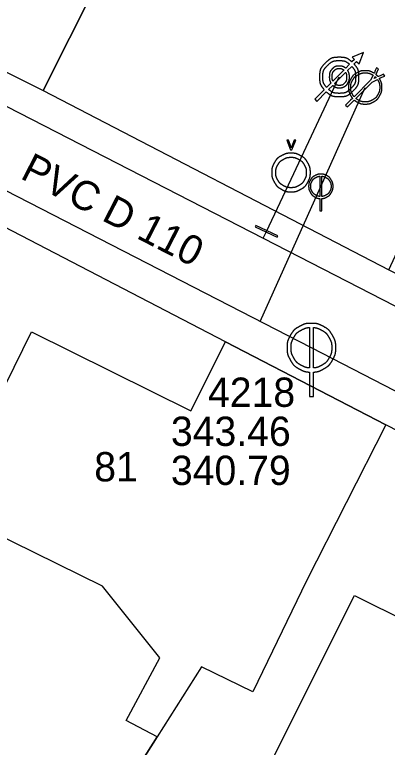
# Model space of a CAD drawing. Extents: x -559654 to -559448, y -1076607 to -1076478.
# Drawn here: x -559557.35 to -559538.26, y -1076565.25 to -1076527.73 of the extents above; entities that cross this region are included whole.
import ezdxf

# ---------------------------------------------------------------- set-up
doc = ezdxf.new("R2010")
doc.units = 0
for name, color, linetype in [('Armatura vodovodní', 7, 'Continuous'), ('Default', 7, 'Continuous'), ('Kanalizační přípojka', 7, 'Continuous'), ('Kanalizační stoka', 7, 'Continuous'), ('Kanalizační šachta', 7, 'Continuous'), ('Odběrné místo', 7, 'Continuous'), ('Odběrné místo na kanalizaci', 7, 'Continuous'), ('Parcela-polygon', 7, 'Continuous'), ('Parcela-text', 7, 'Continuous'), ('Popis šachty', 7, 'Continuous'), ('Vodovodní přípojka', 7, 'Continuous'), ('Vodovodní řad', 7, 'Continuous'), ('Vodovodní šachta', 7, 'Continuous'), ('Řad vodovodní popis', 7, 'Continuous')]:
    doc.layers.add(name, color=color, linetype=linetype)

msp = doc.modelspace()

# ---------------------------------------------------------------- linework, layer by layer
at = {"layer": 'Armatura vodovodní'}
msp.add_lwpolyline([(-559543.905, -1076539.127), (-559543.872, -1076539.056), (-559545.002, -1076538.523), (-559545.036, -1076538.594)], close=True, dxfattribs=at)
at = {"layer": 'Default'}
for points in [[(-559540.724, -1076529.913), (-559541.003, -1076529.913), (-559541.241, -1076530.012), (-559541.438, -1076530.208)], [(-559541.319, -1076530.326), (-559541.155, -1076530.162), (-559540.956, -1076530.08), (-559540.724, -1076530.08)], [(-559540.073, -1076530.15), (-559540.257, -1076529.992), (-559540.474, -1076529.913), (-559540.724, -1076529.913)], [(-559540.724, -1076530.08), (-559540.52, -1076530.08), (-559540.343, -1076530.144), (-559540.191, -1076530.27)], [(-559541.438, -1076530.208), (-559541.635, -1076530.405), (-559541.733, -1076530.642), (-559541.733, -1076530.92)], [(-559541.565, -1076530.92), (-559541.565, -1076530.688), (-559541.483, -1076530.49), (-559541.319, -1076530.326)], [(-559541.087, -1076530.514), (-559541.183, -1076530.615), (-559541.231, -1076530.754), (-559541.231, -1076530.933)], [(-559540.716, -1076530.362), (-559540.868, -1076530.362), (-559540.991, -1076530.413), (-559541.087, -1076530.514)], [(-559540.976, -1076530.589), (-559540.903, -1076530.52), (-559540.816, -1076530.486), (-559540.716, -1076530.486)], [(-559540.449, -1076530.433), (-559540.529, -1076530.386), (-559540.618, -1076530.362), (-559540.716, -1076530.362)], [(-559540.716, -1076530.486), (-559540.645, -1076530.486), (-559540.581, -1076530.504), (-559540.525, -1076530.539)], [(-559540.394, -1076530.472), (-559540.411, -1076530.459), (-559540.429, -1076530.445), (-559540.449, -1076530.433)], [(-559540.084, -1076530.376), (-559539.95, -1076530.53), (-559539.882, -1076530.711), (-559539.882, -1076530.92)], [(-559539.715, -1076530.92), (-559539.715, -1076530.665), (-559539.799, -1076530.443), (-559539.965, -1076530.256)], [(-559541.085, -1076530.935), (-559541.085, -1076530.773), (-559541.048, -1076530.658), (-559540.976, -1076530.589)], [(-559540.525, -1076530.539), (-559540.512, -1076530.548), (-559540.499, -1076530.557), (-559540.488, -1076530.566)], [(-559540.395, -1076530.688), (-559540.395, -1076530.689), (-559540.395, -1076530.69), (-559540.394, -1076530.691)], [(-559540.394, -1076530.691), (-559540.365, -1076530.756), (-559540.35, -1076530.832), (-559540.35, -1076530.919)], [(-559540.266, -1076530.632), (-559540.274, -1076530.616), (-559540.283, -1076530.6), (-559540.293, -1076530.585)], [(-559540.203, -1076530.92), (-559540.203, -1076530.813), (-559540.224, -1076530.717), (-559540.266, -1076530.632)], [(-559539.813, -1076530.709), (-559539.949, -1076530.782), (-559540.055, -1076530.888), (-559540.132, -1076531.025)], [(-559540.035, -1076531.081), (-559539.968, -1076530.962), (-559539.876, -1076530.87), (-559539.757, -1076530.807)], [(-559539.392, -1076530.599), (-559539.537, -1076530.599), (-559539.677, -1076530.635), (-559539.813, -1076530.709)], [(-559539.757, -1076530.807), (-559539.639, -1076530.743), (-559539.517, -1076530.711), (-559539.392, -1076530.711)], [(-559538.973, -1076530.709), (-559539.109, -1076530.635), (-559539.249, -1076530.599), (-559539.392, -1076530.599)], [(-559539.392, -1076530.711), (-559539.268, -1076530.711), (-559539.146, -1076530.743), (-559539.028, -1076530.807)], [(-559539.028, -1076530.807), (-559539.013, -1076530.814), (-559538.999, -1076530.823), (-559538.986, -1076530.831)], [(-559538.935, -1076530.731), (-559538.947, -1076530.724), (-559538.96, -1076530.716), (-559538.973, -1076530.709)], [(-559538.891, -1076530.902), (-559538.874, -1076530.918), (-559538.858, -1076530.934), (-559538.841, -1076530.952)], [(-559538.738, -1076530.901), (-559538.769, -1076530.864), (-559538.803, -1076530.829), (-559538.84, -1076530.799)], [(-559541.733, -1076530.92), (-559541.733, -1076531.171), (-559541.653, -1076531.389), (-559541.493, -1076531.573)], [(-559541.373, -1076531.454), (-559541.501, -1076531.302), (-559541.565, -1076531.125), (-559541.565, -1076530.92)], [(-559541.231, -1076530.933), (-559541.231, -1076531.027), (-559541.211, -1076531.116), (-559541.169, -1076531.201)], [(-559541.169, -1076531.201), (-559541.164, -1076531.212), (-559541.159, -1076531.222), (-559541.153, -1076531.233)], [(-559541.051, -1076531.13), (-559541.073, -1076531.074), (-559541.085, -1076531.009), (-559541.085, -1076530.935)], [(-559540.719, -1076531.352), (-559540.815, -1076531.352), (-559540.897, -1076531.321), (-559540.964, -1076531.257)], [(-559540.454, -1076531.24), (-559540.523, -1076531.315), (-559540.611, -1076531.352), (-559540.719, -1076531.352)], [(-559540.456, -1076531.408), (-559540.376, -1076531.364), (-559540.313, -1076531.299), (-559540.269, -1076531.213)], [(-559540.35, -1076530.919), (-559540.35, -1076531.057), (-559540.385, -1076531.164), (-559540.454, -1076531.24)], [(-559540.269, -1076531.213), (-559540.225, -1076531.127), (-559540.203, -1076531.029), (-559540.203, -1076530.92)], [(-559540.132, -1076531.025), (-559540.208, -1076531.162), (-559540.247, -1076531.305), (-559540.247, -1076531.453)], [(-559540.134, -1076531.453), (-559540.134, -1076531.324), (-559540.101, -1076531.2), (-559540.035, -1076531.081)], [(-559539.882, -1076530.92), (-559539.882, -1076531.152), (-559539.965, -1076531.35), (-559540.129, -1076531.514)], [(-559540.011, -1076531.633), (-559539.814, -1076531.436), (-559539.715, -1076531.199), (-559539.715, -1076530.92)], [(-559538.771, -1076531.046), (-559538.764, -1076531.057), (-559538.757, -1076531.069), (-559538.749, -1076531.081)], [(-559538.749, -1076531.081), (-559538.683, -1076531.2), (-559538.65, -1076531.324), (-559538.65, -1076531.453)], [(-559538.653, -1076531.024), (-559538.659, -1076531.014), (-559538.665, -1076531.004), (-559538.671, -1076530.994)], [(-559538.538, -1076531.453), (-559538.538, -1076531.305), (-559538.576, -1076531.162), (-559538.653, -1076531.024)], [(-559540.724, -1076531.759), (-559540.933, -1076531.759), (-559541.114, -1076531.693), (-559541.267, -1076531.561)], [(-559541.057, -1076531.351), (-559541.036, -1076531.369), (-559541.013, -1076531.386), (-559540.988, -1076531.401)], [(-559540.988, -1076531.401), (-559540.909, -1076531.45), (-559540.818, -1076531.475), (-559540.717, -1076531.475)], [(-559540.129, -1076531.514), (-559540.293, -1076531.677), (-559540.492, -1076531.759), (-559540.724, -1076531.759)], [(-559540.724, -1076531.927), (-559540.445, -1076531.927), (-559540.208, -1076531.829), (-559540.011, -1076531.633)], [(-559540.717, -1076531.475), (-559540.624, -1076531.475), (-559540.537, -1076531.452), (-559540.456, -1076531.408)], [(-559540.247, -1076531.453), (-559540.247, -1076531.601), (-559540.209, -1076531.743), (-559540.133, -1076531.879)], [(-559540.036, -1076531.822), (-559540.101, -1076531.705), (-559540.134, -1076531.582), (-559540.134, -1076531.453)], [(-559538.65, -1076531.453), (-559538.65, -1076531.582), (-559538.683, -1076531.705), (-559538.748, -1076531.823)], [(-559538.65, -1076531.879), (-559538.575, -1076531.743), (-559538.538, -1076531.601), (-559538.538, -1076531.453)], [(-559541.386, -1076531.681), (-559541.2, -1076531.845), (-559540.979, -1076531.927), (-559540.724, -1076531.927)], [(-559540.133, -1076531.879), (-559540.107, -1076531.928), (-559540.076, -1076531.973), (-559540.041, -1076532.014)], [(-559539.96, -1076531.933), (-559539.989, -1076531.899), (-559540.014, -1076531.862), (-559540.036, -1076531.822)], [(-559539.761, -1076532.097), (-559539.802, -1076532.074), (-559539.839, -1076532.049), (-559539.872, -1076532.02)], [(-559538.748, -1076531.823), (-559538.813, -1076531.94), (-559538.905, -1076532.032), (-559539.023, -1076532.097)], [(-559538.967, -1076532.195), (-559538.831, -1076532.12), (-559538.726, -1076532.014), (-559538.65, -1076531.879)], [(-559539.954, -1076532.101), (-559539.912, -1076532.137), (-559539.866, -1076532.168), (-559539.817, -1076532.194)], [(-559539.817, -1076532.194), (-559539.681, -1076532.27), (-559539.54, -1076532.308), (-559539.392, -1076532.308)], [(-559539.392, -1076532.195), (-559539.52, -1076532.195), (-559539.643, -1076532.162), (-559539.761, -1076532.097)], [(-559539.023, -1076532.097), (-559539.141, -1076532.163), (-559539.264, -1076532.195), (-559539.392, -1076532.195)], [(-559539.392, -1076532.308), (-559539.244, -1076532.308), (-559539.102, -1076532.27), (-559538.967, -1076532.195)], [(-559543.183, -1076534.547), (-559543.185, -1076534.529), (-559543.189, -1076534.518), (-559543.193, -1076534.513)], [(-559543.169, -1076534.513), (-559543.174, -1076534.522), (-559543.178, -1076534.534), (-559543.183, -1076534.547)], [(-559543.678, -1076534.951), (-559543.836, -1076535.035), (-559543.959, -1076535.157), (-559544.048, -1076535.316)], [(-559543.193, -1076534.824), (-559543.359, -1076534.824), (-559543.521, -1076534.866), (-559543.678, -1076534.951)], [(-559543.574, -1076535.134), (-559543.45, -1076535.066), (-559543.323, -1076535.033), (-559543.193, -1076535.033)], [(-559542.706, -1076534.951), (-559542.864, -1076534.866), (-559543.027, -1076534.824), (-559543.193, -1076534.824)], [(-559543.193, -1076535.033), (-559543.061, -1076535.033), (-559542.933, -1076535.066), (-559542.809, -1076535.134)], [(-559542.335, -1076535.316), (-559542.424, -1076535.157), (-559542.548, -1076535.035), (-559542.706, -1076534.951)], [(-559544.048, -1076535.316), (-559544.136, -1076535.476), (-559544.181, -1076535.642), (-559544.181, -1076535.815)], [(-559543.866, -1076535.422), (-559543.796, -1076535.297), (-559543.698, -1076535.201), (-559543.574, -1076535.134)], [(-559542.809, -1076535.134), (-559542.684, -1076535.201), (-559542.587, -1076535.297), (-559542.516, -1076535.422)], [(-559542.202, -1076535.815), (-559542.202, -1076535.642), (-559542.246, -1076535.476), (-559542.335, -1076535.316)], [(-559543.972, -1076535.815), (-559543.972, -1076535.679), (-559543.937, -1076535.548), (-559543.866, -1076535.422)], [(-559542.516, -1076535.422), (-559542.446, -1076535.548), (-559542.41, -1076535.679), (-559542.41, -1076535.815)], [(-559544.181, -1076535.815), (-559544.181, -1076535.986), (-559544.137, -1076536.15), (-559544.049, -1076536.306)], [(-559543.868, -1076536.202), (-559543.938, -1076536.079), (-559543.972, -1076535.95), (-559543.972, -1076535.815)], [(-559542.41, -1076535.815), (-559542.41, -1076535.95), (-559542.445, -1076536.079), (-559542.515, -1076536.202)], [(-559542.332, -1076536.306), (-559542.245, -1076536.15), (-559542.202, -1076535.986), (-559542.202, -1076535.815)], [(-559541.972, -1076535.977), (-559542.072, -1076536.031), (-559542.149, -1076536.108), (-559542.205, -1076536.208)], [(-559542.115, -1076536.261), (-559542.069, -1076536.178), (-559542.004, -1076536.113), (-559541.921, -1076536.068)], [(-559541.665, -1076535.897), (-559541.77, -1076535.897), (-559541.873, -1076535.924), (-559541.972, -1076535.977)], [(-559541.921, -1076536.068), (-559541.849, -1076536.03), (-559541.781, -1076536.008), (-559541.716, -1076536.002)], [(-559541.357, -1076535.977), (-559541.456, -1076535.924), (-559541.559, -1076535.897), (-559541.665, -1076535.897)], [(-559541.613, -1076536.002), (-559541.547, -1076536.008), (-559541.478, -1076536.03), (-559541.408, -1076536.068)], [(-559541.408, -1076536.068), (-559541.325, -1076536.113), (-559541.26, -1076536.178), (-559541.213, -1076536.261)], [(-559541.124, -1076536.208), (-559541.18, -1076536.108), (-559541.258, -1076536.031), (-559541.357, -1076535.977)], [(-559544.049, -1076536.306), (-559543.962, -1076536.462), (-559543.839, -1076536.584), (-559543.682, -1076536.672)], [(-559543.579, -1076536.489), (-559543.702, -1076536.42), (-559543.799, -1076536.325), (-559543.868, -1076536.202)], [(-559543.193, -1076536.591), (-559543.328, -1076536.591), (-559543.456, -1076536.557), (-559543.579, -1076536.489)], [(-559542.803, -1076536.489), (-559542.926, -1076536.557), (-559543.056, -1076536.591), (-559543.193, -1076536.591)], [(-559542.515, -1076536.202), (-559542.584, -1076536.325), (-559542.68, -1076536.42), (-559542.803, -1076536.489)], [(-559542.697, -1076536.672), (-559542.54, -1076536.584), (-559542.418, -1076536.462), (-559542.332, -1076536.306)], [(-559542.205, -1076536.208), (-559542.262, -1076536.308), (-559542.29, -1076536.413), (-559542.29, -1076536.522)], [(-559542.29, -1076536.522), (-559542.29, -1076536.629), (-559542.262, -1076536.733), (-559542.207, -1076536.832)], [(-559542.185, -1076536.522), (-559542.185, -1076536.431), (-559542.161, -1076536.344), (-559542.115, -1076536.261)], [(-559542.116, -1076536.779), (-559542.162, -1076536.697), (-559542.185, -1076536.611), (-559542.185, -1076536.522)], [(-559541.213, -1076536.261), (-559541.166, -1076536.344), (-559541.142, -1076536.431), (-559541.142, -1076536.522)], [(-559541.142, -1076536.522), (-559541.142, -1076536.611), (-559541.165, -1076536.697), (-559541.211, -1076536.779)], [(-559541.04, -1076536.522), (-559541.04, -1076536.413), (-559541.068, -1076536.308), (-559541.124, -1076536.208)], [(-559541.121, -1076536.832), (-559541.067, -1076536.733), (-559541.04, -1076536.629), (-559541.04, -1076536.522)], [(-559543.682, -1076536.672), (-559543.525, -1076536.759), (-559543.362, -1076536.803), (-559543.193, -1076536.803)], [(-559543.193, -1076536.803), (-559543.02, -1076536.803), (-559542.855, -1076536.759), (-559542.697, -1076536.672)], [(-559542.207, -1076536.832), (-559542.151, -1076536.931), (-559542.074, -1076537.008), (-559541.975, -1076537.064)], [(-559541.923, -1076536.971), (-559542.006, -1076536.925), (-559542.071, -1076536.862), (-559542.116, -1076536.779)], [(-559541.211, -1076536.779), (-559541.256, -1076536.862), (-559541.32, -1076536.925), (-559541.403, -1076536.971)], [(-559541.352, -1076537.064), (-559541.253, -1076537.008), (-559541.176, -1076536.931), (-559541.121, -1076536.832)], [(-559541.975, -1076537.064), (-559541.888, -1076537.113), (-559541.802, -1076537.139), (-559541.716, -1076537.144)], [(-559541.716, -1076537.039), (-559541.784, -1076537.034), (-559541.853, -1076537.012), (-559541.923, -1076536.971)], [(-559541.403, -1076536.971), (-559541.475, -1076537.012), (-559541.545, -1076537.034), (-559541.613, -1076537.039)], [(-559541.613, -1076537.144), (-559541.527, -1076537.139), (-559541.44, -1076537.113), (-559541.352, -1076537.064)], [(-559542.148, -1076543.537), (-559542.36, -1076543.537), (-559542.565, -1076543.591), (-559542.763, -1076543.698)], [(-559541.534, -1076543.698), (-559541.733, -1076543.591), (-559541.938, -1076543.537), (-559542.148, -1076543.537)], [(-559542.763, -1076543.698), (-559542.962, -1076543.806), (-559543.117, -1076543.959), (-559543.23, -1076544.16)], [(-559543.051, -1076544.266), (-559542.959, -1076544.099), (-559542.829, -1076543.971), (-559542.663, -1076543.881)], [(-559542.663, -1076543.881), (-559542.52, -1076543.805), (-559542.382, -1076543.761), (-559542.251, -1076543.749)], [(-559542.045, -1076543.749), (-559541.914, -1076543.761), (-559541.777, -1076543.805), (-559541.635, -1076543.881)], [(-559541.635, -1076543.881), (-559541.469, -1076543.971), (-559541.339, -1076544.099), (-559541.246, -1076544.266)], [(-559541.066, -1076544.16), (-559541.179, -1076543.959), (-559541.335, -1076543.806), (-559541.534, -1076543.698)], [(-559543.23, -1076544.16), (-559543.342, -1076544.36), (-559543.398, -1076544.569), (-559543.398, -1076544.787)], [(-559543.19, -1076544.787), (-559543.19, -1076544.606), (-559543.144, -1076544.433), (-559543.051, -1076544.266)], [(-559541.246, -1076544.266), (-559541.152, -1076544.433), (-559541.106, -1076544.606), (-559541.106, -1076544.787)], [(-559540.898, -1076544.787), (-559540.898, -1076544.569), (-559540.954, -1076544.36), (-559541.066, -1076544.16)], [(-559543.398, -1076544.787), (-559543.398, -1076545.003), (-559543.343, -1076545.211), (-559543.233, -1076545.41)], [(-559543.054, -1076545.305), (-559543.145, -1076545.14), (-559543.19, -1076544.968), (-559543.19, -1076544.787)], [(-559541.106, -1076544.787), (-559541.106, -1076544.968), (-559541.151, -1076545.14), (-559541.242, -1076545.305)], [(-559541.063, -1076545.41), (-559540.953, -1076545.211), (-559540.898, -1076545.003), (-559540.898, -1076544.787)], [(-559543.233, -1076545.41), (-559543.123, -1076545.608), (-559542.969, -1076545.762), (-559542.771, -1076545.871)], [(-559542.668, -1076545.688), (-559542.834, -1076545.597), (-559542.963, -1076545.469), (-559543.054, -1076545.305)], [(-559541.242, -1076545.305), (-559541.333, -1076545.469), (-559541.461, -1076545.597), (-559541.626, -1076545.688)], [(-559541.525, -1076545.871), (-559541.327, -1076545.762), (-559541.173, -1076545.608), (-559541.063, -1076545.41)], [(-559542.771, -1076545.871), (-559542.596, -1076545.969), (-559542.423, -1076546.023), (-559542.251, -1076546.035)], [(-559542.251, -1076545.822), (-559542.387, -1076545.812), (-559542.526, -1076545.768), (-559542.668, -1076545.688)], [(-559541.626, -1076545.688), (-559541.769, -1076545.768), (-559541.909, -1076545.812), (-559542.045, -1076545.822)], [(-559542.045, -1076546.035), (-559541.873, -1076546.023), (-559541.7, -1076545.969), (-559541.525, -1076545.871)]]:
    msp.add_open_spline(points, degree=2, dxfattribs=at)
at = {"layer": 'Kanalizační přípojka'}
msp.add_lwpolyline([(-559544.766, -1076543.44), (-559541.665, -1076536.522), (-559539.392, -1076531.453)], dxfattribs=at)
at = {"layer": 'Kanalizační stoka'}
for points in [[(-559542.148, -1076544.787), (-559590.298, -1076520.017)], [(-559500.698, -1076566.177), (-559542.148, -1076544.787)]]:
    msp.add_lwpolyline(points, dxfattribs=at)
at = {"layer": 'Kanalizační šachta'}
for points in [[(-559541.716, -1076536.002), (-559541.716, -1076537.039)], [(-559541.613, -1076537.039), (-559541.613, -1076536.002)], [(-559541.716, -1076537.772), (-559541.613, -1076537.772), (-559541.613, -1076537.144)], [(-559541.716, -1076537.144), (-559541.716, -1076537.772)], [(-559542.251, -1076543.749), (-559542.251, -1076545.822)], [(-559542.045, -1076545.822), (-559542.045, -1076543.749)], [(-559542.251, -1076547.287), (-559542.045, -1076547.287), (-559542.045, -1076546.035)], [(-559542.251, -1076546.035), (-559542.251, -1076547.287)]]:
    msp.add_lwpolyline(points, dxfattribs=at)
at = {"layer": 'Odběrné místo'}
for points in [[(-559539.965, -1076530.256), (-559539.835, -1076530.127), (-559539.698, -1076530.256), (-559539.476, -1076529.67), (-559540.063, -1076529.911), (-559539.945, -1076530.022), (-559540.073, -1076530.15)], [(-559540.191, -1076530.27), (-559540.394, -1076530.472)], [(-559540.293, -1076530.585), (-559540.084, -1076530.376)], [(-559540.488, -1076530.566), (-559541.051, -1076531.13)], [(-559540.964, -1076531.257), (-559540.395, -1076530.688)], [(-559541.153, -1076531.233), (-559541.373, -1076531.454)], [(-559541.493, -1076531.573), (-559541.976, -1076532.058), (-559541.875, -1076532.17)], [(-559541.267, -1076531.561), (-559541.057, -1076531.351)], [(-559541.875, -1076532.17), (-559541.386, -1076531.681)]]:
    msp.add_lwpolyline(points, dxfattribs=at)
at = {"layer": 'Odběrné místo na kanalizaci'}
for points in [[(-559538.84, -1076530.799), (-559538.831, -1076530.78), (-559538.784, -1076530.66), (-559538.718, -1076530.499), (-559538.819, -1076530.453), (-559538.879, -1076530.595), (-559538.925, -1076530.713), (-559538.935, -1076530.731)], [(-559538.986, -1076530.831), (-559539.118, -1076531.089), (-559539.96, -1076531.933)], [(-559538.94, -1076531.001), (-559538.891, -1076530.902)], [(-559538.671, -1076530.994), (-559538.653, -1076530.984), (-559538.535, -1076530.939), (-559538.393, -1076530.878), (-559538.449, -1076530.783), (-559538.599, -1076530.845), (-559538.72, -1076530.892), (-559538.738, -1076530.901)], [(-559539.872, -1076532.02), (-559539.032, -1076531.18), (-559538.771, -1076531.046)], [(-559538.841, -1076530.952), (-559538.94, -1076531.001)], [(-559540.041, -1076532.014), (-559540.053, -1076532.025), (-559540.143, -1076532.114), (-559540.395, -1076532.365), (-559540.307, -1076532.454)], [(-559540.307, -1076532.454), (-559540.055, -1076532.203), (-559539.965, -1076532.113), (-559539.954, -1076532.101)]]:
    msp.add_lwpolyline(points, dxfattribs=at)
at = {"layer": 'Parcela-polygon'}
for points in [[(-559598.18, -1076518.16), (-559629.27, -1076502.23), (-559633.72, -1076500.39), (-559623.33, -1076497.36), (-559616.19, -1076501.28), (-559573.81, -1076522.62), (-559555.89, -1076531.62), (-559538.18, -1076540.8), (-559520.56, -1076549.81), (-559502.55, -1076559.13), (-559485.32, -1076568.19), (-559489.07, -1076574.14), (-559505.11, -1076565.7), (-559518.69, -1076558.79), (-559538.34, -1076548.73), (-559546.54, -1076544.48), (-559559.21, -1076537.91), (-559568.79, -1076532.99), (-559577, -1076528.76), (-559595.22, -1076519.64)], [(-559556.49, -1076543.97), (-559548.32, -1076548.02), (-559546.54, -1076544.48), (-559538.34, -1076548.73), (-559542.4, -1076556.72), (-559545.15, -1076562.4), (-559547.78, -1076561.13), (-559550.05, -1076564.71), (-559551.63, -1076563.88), (-559549.91, -1076560.67), (-559552.84, -1076557), (-559560.94, -1076553.02)], [(-559545.74, -1076569.06), (-559539.94, -1076557.48), (-559534.35, -1076560.25), (-559532.8, -1076557.23), (-559527.46, -1076559.95), (-559529.02, -1076563.03), (-559525.28, -1076564.87), (-559528.02, -1076570.62), (-559530.78, -1076569.31), (-559530.97, -1076569.71), (-559536.96, -1076566.67), (-559539.65, -1076572.09)]]:
    msp.add_lwpolyline(points, close=True, dxfattribs=at)
for points in [[(-559548.356, -1076508.596), (-559549.45, -1076510.66), (-559551.72, -1076509.51), (-559557.46, -1076506.54), (-559559.19, -1076509.84), (-559565.46, -1076506.3), (-559573.81, -1076522.62), (-559555.89, -1076531.62), (-559545.04, -1076510.049)], [(-559545.04, -1076510.049), (-559555.89, -1076531.62), (-559538.18, -1076540.8), (-559527.504, -1076517.73)], [(-559551.999, -1076568.129), (-559551.22, -1076566.57), (-559550.05, -1076564.71), (-559551.63, -1076563.88), (-559549.91, -1076560.67), (-559552.84, -1076557), (-559560.94, -1076553.02), (-559556.49, -1076543.97), (-559548.32, -1076548.02), (-559546.54, -1076544.48), (-559559.21, -1076537.91), (-559569.856, -1076558.926)], [(-559529.198, -1076579.881), (-559524.71, -1076570.87), (-559518.69, -1076558.79), (-559538.34, -1076548.73), (-559542.4, -1076556.72), (-559545.15, -1076562.4), (-559547.78, -1076561.13), (-559550.05, -1076564.71), (-559551.22, -1076566.57), (-559551.999, -1076568.129)], [(-559539.65, -1076572.09), (-559545.74, -1076569.06), (-559539.94, -1076557.48), (-559534.35, -1076560.25), (-559532.8, -1076557.23), (-559527.46, -1076559.95), (-559529.02, -1076563.03), (-559525.28, -1076564.87), (-559528.02, -1076570.62), (-559530.82, -1076576.47), (-559539.65, -1076572.09)]]:
    msp.add_lwpolyline(points, dxfattribs=at)
at = {"layer": 'Vodovodní přípojka'}
msp.add_lwpolyline([(-559544.618, -1076539.173), (-559544.454, -1076538.826), (-559543.191, -1076536.147), (-559540.726, -1076530.92)], dxfattribs=at)
at = {"layer": 'Vodovodní řad'}
msp.add_lwpolyline([(-559593.267, -1076491.395), (-559624.029, -1076495.839), (-559624.9, -1076495.951), (-559625.488, -1076496.027), (-559625.404, -1076497.654), (-559619.475, -1076500.701), (-559618.245, -1076501.333), (-559615.438, -1076502.776), (-559591.192, -1076515.237), (-559582.087, -1076519.916), (-559544.618, -1076539.173), (-559534.23, -1076544.512), (-559532.371, -1076545.439), (-559530.757, -1076546.244), (-559525.83, -1076548.702), (-559513.543, -1076555.186), (-559509.507, -1076557.365), (-559508.97, -1076557.619), (-559494.604, -1076565.581), (-559494.539, -1076565.616), (-559485.627, -1076570.145)], dxfattribs=at)
at = {"layer": 'Vodovodní šachta'}
for points in [[(-559543.193, -1076534.513), (-559543.316, -1076534.154), (-559543.412, -1076534.154), (-559543.217, -1076534.657)], [(-559543.217, -1076534.657), (-559543.149, -1076534.657), (-559542.95, -1076534.154), (-559543.039, -1076534.154), (-559543.169, -1076534.513)]]:
    msp.add_lwpolyline(points, dxfattribs=at)

# ---------------------------------------------------------------- texts
at = {"layer": 'Parcela-text'}
msp.add_text('81', height=1.5, dxfattribs=at).set_placement((-559553.27, -1076551.63))
at = {"layer": 'Popis šachty'}
for s, p in [('4218', (-559547.444, -1076547.814)), ('343.46', (-559549.343, -1076549.814)), ('340.79', (-559549.343, -1076551.814))]:
    msp.add_text(s, height=1.5, dxfattribs=at).set_placement(p)
at = {"layer": 'Řad vodovodní popis'}
msp.add_text('PVC D 110', height=1.5, rotation=332.7992, dxfattribs=at).set_placement((-559557.113, -1076536.088))

doc.saveas('drawing.dxf')
